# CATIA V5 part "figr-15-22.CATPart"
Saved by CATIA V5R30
Part number: Part1
Bounding box of the stored display mesh (mm): x -75 to 76, y -66.397 to 33.603, z 0 to 100
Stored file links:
  D:\PROJECTS\CATIA V56R 2020\Resources\Parts File\c15_catia_v5_6r2020_prt\figr-15-22.CATPart
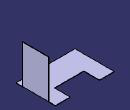
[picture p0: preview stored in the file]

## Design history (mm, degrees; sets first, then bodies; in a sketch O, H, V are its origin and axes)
SheetMetalParameters1: Thickness 1, BendRadius 1, KFactor 0.325257 {= log(min(100,max(20*SheetMetalParameters1.BendRadius,SheetMetalParameters1.Thickness)/SheetMetalParameters1.Thickness))/log(100)/2}, ReliefRadialLength 1, ReliefAxialLength 2, MinimumBendRadius 0
Body1 (main body)
  Sketch1 on xy-plane, origin (0, 0, 0), H (1, 0, 0), V (0, 1, 0)
    line L1 (-37.5, 33.6029) -> (-37.5, -6.3971)
    line L2 (-37.5, -6.3971) -> (37.5, -6.3971)
    line L3 (37.5, -6.3971) -> (37.5, 33.6029)
    line L4 (37.5, 33.6029) -> (75, 33.6029)
    line L5 (75, 33.6029) -> (75, -66.3971)
    line L6 (75, -66.3971) -> (-75, -66.3971)
    line L7 (-75, -66.3971) -> (-75, 33.6029)
    point P8 (-75, 33.6029)
    line L8 (-75, 33.6029) -> (-37.5, 33.6029)
    length L7 = 100
    length L1 = 40
    length L6 = 150
    distance L1 L3 = 75
    vertical: L1 V, L3 V, L5 V, L7 V
    horizontal: L2 H, L4 H, L6 H, L8 H
    coincidence: P8 L4
    symmetry: L7 L5 V, L1 L3 V
  Wall1: Thickness 1, Profile Sketch1
  d_NewWallOnEdge1: NewWallOnEdge_Edge edge [face of Wall1 | face of Wall1], NewWallOnEdge_Length 100, NewWallOnEdge_HeightLimitOffset 0, NewWallOnEdge_WidthOffset1 -16, NewWallOnEdge_WidthOffset2 -17, NewWallOnEdge_Angle 90, NewWallOnEdge_BendRadiusValue 1 {= SheetMetalParameters1.BendRadius}, NewWallOnEdge_BendTable SheetMetalParameters1, KFacteur 0.325257 {= log(min(100,max(20*d_NewWallOnEdge1.Radius,SheetMetalParameters1.Thickness)/SheetMetalParameters1.Thickness))/log(100)/2}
